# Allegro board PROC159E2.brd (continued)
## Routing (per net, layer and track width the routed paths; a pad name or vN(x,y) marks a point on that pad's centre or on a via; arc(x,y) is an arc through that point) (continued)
V3V3_XDS_FB: length 4.1
  TOP w0.381: U51.5 R332.2 ; R332.2 R333.1 ; R332.2 C248.2
VBAT_LIN: length 2.4
  TOP w0.381: D7.2 J9.1
VBAT_XDS: length 3.8
  TOP w0.381: R334.2 C262.1 33.54,87.49 v1(33.54,88.74)
  BOTTOM w0.203: U52.68 v1(33.54,88.74)
VBUS_DET: length 1.2
  BOTTOM w0.203: U17.4 103.18,13.53 R5.1
VBUS_MAIN: length 4.5
  TOP w0.381: v1(97.15,17.89) 96.9,17.64 U4.2
  BOTTOM w0.381: v1(97.75,23.8) v1(98.77,23.8) R11.1 R10.1
  vias: v1(97.15,18.78) v1(98.04,18.78) v1(98.04,17.89)
VBUS_USBC: length 18.1
  TOP w0.254: R1.1 101.96,13.55 102.08,13.68 U2.5
  TOP w0.305: 105.79,18.28 106.03,18.03 J1.A4 107.55,18.03 107.56,18.02 107.82,18.28 J1.B9 ; J1.B4 107.85,20.78 107.56,21.07 107.53,21.03 J1.A9 106.05,21.03 ; 106.05,21.03 105.66,20.64 105.66,20.43 ; 106.05,21.03 105.53,21.55 105.53,21.58
  TOP w0.381: R1.1 C2.1 v1(100.19,14.64)
  BOTTOM w0.203: U17.12 99.66,13.93 C1.1
  BOTTOM w0.254: v1(100.19,14.64) 99.67,14.64 99.41,14.39 C1.1
  BOTTOM w0.381: R6.1 103.28,10.62 103.02,10.37 R4.1 R3.1 v1(100.2,10.37) ; R5.2 v1(104.9,13.91)
  vias: v1(102.36,21.83) v1(102.36,21.07) v1(102.36,20.31) v1(102.36,19.67) v1(103.25,20.31) v1(103.25,19.67) v1(104.01,20.31) v1(104.01,19.67) v1(104.01,18.53) v1(105.02,18.53)
VBUS_XDS110: length 7.1
  TOP w0.381: U51.8 v1(17.05,103.83)
  BOTTOM w0.305: v1(15.11,99.3) 13.16,97.35 U53.6
  BOTTOM w0.381: R339.2 v1(19.93,83.05) ; R340.1 v1(21.36,103.97)
VCC2V5_PG: length 21.7
  TOP w0.254: v1(100.13,85.16) 99.49,85.8 98.62,85.8 98.06,85.24 98.06,82.79 v1(96.21,80.94) ; v1(100.13,85.16) 100.13,86.24 100.74,86.85 101.19,86.85 104.61,90.27 R81.1 ; v1(100.13,85.16) 100.47,84.82 R80.2
  BOTTOM w0.254: U14.5 v1(100.13,85.16)
  BOTTOM w0.381: v1(96.21,80.94) 95.59,80.32 93.76,80.32 93.37,80.71 U16.3
VCC3V3_XDS: length 76.7
  TOP w0.381: R354.1 v1(27.17,100.67) ; 19.98,99.86 R332.1 C248.1 ; R334.1 v1(35.56,86.22) ; R370.1 R369.1 ; R369.1 R368.1 R367.1 R366.1 R365.1 ; R369.1 v1(30.09,100.18) ; U57.1 33.33,106.68 C273.2 v1(31.64,107.28) ; R306.2 v1(37.89,78.04) 37.86,78.08 C352.1
  BOTTOM w0.203: U52.8 25.14,103.94 24.78,104.31 24.74,104.27 U52.7 ; U52.28 33.14,103.84 32.68,104.31 32.34,103.97 U52.26 ; U52.79 29.14,86.13 29.19,86.09 C252.1 ; U52.90 v1(24.74,88.72) ; C253.1 37.44,95.85 37.3,95.71 U52.47 ; U52.101 v1(22.19,90.51) ; U52.122 22.21,98.91 v1(22.22,98.92) ; C254.1 19.19,94.75 19.75,95.31 U52.113 ; C250.1 27.99,104.45 28.34,104.1 U52.16 ; C255.1 33.14,85.6 U52.69 ; U52.52 37.4,93.71 37.51,93.82 37.22,94.11 U52.51 ; U52.39 v1(34.93,98.91)
  BOTTOM w0.381: 24.78,104.31 C251.1 v1(24.78,105.91) ; R377.1 v1(18.51,82.41) ; R346.2 R345.2 v1(40.51,89) ; U31.1 C182.2 v1(40.89,87.24) ; v1(32.33,105.91) 32.68,105.56 C258.1 32.68,104.31 ; v1(38.98,93.82) C257.1 37.51,93.82 ; C253.1 v1(38.98,95.85) ; C180.2 v1(32.93,82.41) ; C180.2 34.14,81.65 R353.1 ; C180.2 U32.8 ; C254.1 v1(17.65,94.75) ; U54.8 40.91,96.25 C266.1 v1(40,96.24) 39.67,96.57 R356.1 R357.1 ; C252.1 v1(29.19,84.57) ; R348.2 v1(37.31,83.57) ; U58.1 17.24,81.14 C274.1 v1(16.51,81.17) ; R347.2 39.67,83.25 39.8,83.12 R360.1 v1(39.11,82.51) ; C255.1 v1(33.29,84.57) ; U56.1 41.21,79.97 41.11,79.87 C271.2 v1(40.41,80.48) ; C250.1 v1(27.99,105.91) ; R359.1 v1(39.11,81.24)
  vias: v1(22.22,100.06)
VCC_1V1: length 29.4
  TOP w0.254: U15.1 107.45,88.02 C97.1 107.49,87.56
  TOP w0.381: v1(99.15,78.16) 99.81,78.16 101.7,80.05 103.51,80.05 107.49,84.03 TP30.1 107.49,87.56
  BOTTOM w0.381: FL4.1 87.76,79.55 88.05,79.84 93.09,79.84 93.81,79.12 98.19,79.12 v1(99.15,78.16)
VCC_1V2: length 28.4
  TOP w0.381: v1(70.25,43.19) 70.38,43.06 C120.1 C121.1 ; U1.D10 v1(60.98,44.83) ; U1.N5 v1(56.18,36.83) ; U1.G6 v1(56.98,42.43) ; U1.G13 v1(63.38,42.43) ; U1.E9 v1(59.38,44.03) ; U1.K6 v1(56.98,39.23) ; U1.K13 v1(63.38,39.23) ; U1.G14 v1(64.18,42.43) ; U1.H3 v1(54.58,41.63) ; U1.F9 v1(59.38,43.23) ; U1.J15 v1(64.98,40.83) ; U1.N13 v1(63.38,36.83) ; U1.J16 v1(65.78,40.83) ; U1.N14 v1(64.18,36.83) ; U1.N6 v1(56.98,36.83) ; U1.E11 v1(61.78,44.03) ; U1.G5 v1(56.18,42.43) ; U1.K5 v1(56.18,39.23) ; U1.K14 v1(64.18,39.23) ; U1.R9 v1(59.38,35.23) ; U1.F11 v1(61.78,43.23)
  BOTTOM w0.305: C112.1 64.12,39.29 v1(64.18,39.23) ; v1(63.38,36.83) 63.25,36.96 C116.1 ; C133.1 61.65,43.1 v1(61.78,43.23) ; C118.1 60.87,44.72 v1(60.98,44.83) ; C124.1 64.87,40.94 v1(64.98,40.83) ; v1(56.18,39.23) 56.22,39.27 C129.1 ; C126.1 59.25,43.1 v1(59.38,43.23) 59.49,43.12 C111.1 ; C131.1 56.87,39.12 v1(56.98,39.23) 56.99,39.23 C122.1 ; C132.1 64.05,42.56 v1(64.18,42.43) ; C110.1 59.25,43.9 v1(59.38,44.03) ; C115.1 63.25,42.56 v1(63.38,42.43) ; v1(61.78,44.03) 61.89,43.92 C127.1 ; v1(56.98,36.83) 56.85,36.96 C130.1 ; C117.1 56.05,36.96 v1(56.18,36.83) ; v1(56.18,42.43) 56.29,42.54 C128.1 ; C113.1 64.05,36.96 v1(64.18,36.83) ; v1(56.98,42.43) 57.09,42.54 C125.1 ; v1(63.38,39.23) 63.27,39.34 C114.1 C123.1
  BOTTOM w0.381: R75.2 84.2,49.69 v1(84.2,49.01) ; C102.1 v1(73.87,43.19) C103.1 C119.1 v1(70.25,43.19)
  vias: v1(81.53,49.01) v1(81.53,48.12) v1(81.53,47.23) v1(82.42,49.01) v1(82.42,48.12) v1(82.42,47.23) v1(83.31,49.01) v1(83.31,48.12) v1(83.31,47.23) v1(84.2,48.12) v1(84.2,47.23)
VCC_1V2_N: length 3.8
  BOTTOM w0.108: R70.2 87.65,50.33 87.65,49.92 87.4,49.67 86.12,49.67 85.77,50.02 85.41,50.02 R75.1
VCC_1V2_P: length 3.4
  BOTTOM w0.108: R75.4 85.43,50.28 85.88,50.28 86.23,49.93 87.3,49.93 87.39,50.02 87.39,50.33 R68.2
VCC_1V8_LDO4: length 11
  TOP w0.254: v1(106.48,48.63) C72.1 106.48,47.2 106.69,46.99 U7.30
  TOP w0.381: v1(39.46,22.69) 39.45,22.7 SW7.1 ; v1(105.14,57.14) 104.45,57.14 103.92,57.68 R3833.1
  BOTTOM w0.381: TP20.1 105.14,56.51 v1(105.14,57.14) ; R36.2 v1(112.57,34.4)
VCC_2V5_EN: length 1.8
  TOP w0.147: R78.1 v1(99.21,85.16)
  BOTTOM w0.254: v1(99.21,85.16) 99.63,85.58 U14.6
VCC_5V0: length 6.3
  TOP w0.305: U29.3 23.41,22.91 C174.2
  TOP w0.381: v1(66.29,4.43) 66.66,4.43 67.04,4.05 J15.117 ; C174.2 v1(24.51,22.58)
  BOTTOM w0.381: FB1.2 24.49,22.59 v1(24.51,22.58)
VCC_6V0_BBOUT: length 12.7
  TOP w0.254: 100.69,46.22 U7.42 ; C80.1 94.96,55.92 93.13,57.75 U9.6 ; 101.19,46.33 U7.41
  TOP w0.305: 101.29,47.45 101.29,47.49
  TOP w0.381: C345.1 90.51,47.15 90.23,46.87 U66.6 ; 101.19,46.33 101.46,46.6 101.46,47.38 101.35,47.49 C31.1 101.16,47.37 100.69,46.9 100.69,46.22
  vias: v1(100.83,53.83) v1(100.83,51.8) v1(101.21,49.64) v1(101.21,48.25) v1(101.6,53.83) v1(101.6,51.8)
VCC_PLDO1: length 8.5
  TOP w0.305: U7.20 107.19,36.45 107.26,36.38 107.26,35.85 107.78,35.33 C76.1
  TOP w0.381: v1(107.78,33.56) C76.1
  BOTTOM w0.381: C74.1 110.01,35.54 110.87,35.54 111.21,35.88 111.21,37.26 J3.1
VCC_PLDO2: length 6.3
  TOP w0.254: v1(107.59,48.63) C79.1 107.59,47.24 107.19,46.84 U7.29
  BOTTOM w0.381: v1(107.82,50.91) 107.82,50.34 107.59,50.12 v1(107.59,48.63)
VDD1V1A: length 16.5
  TOP w0.381: v1(93.47,68.84) C195.1 ; C197.1 v1(87.28,75.08) ; C191.1 C192.1 85.3,68.84 v1(84.32,68.84)
  BOTTOM w0.305: U35.31 v1(84.32,68.84) ; U35.6 v1(93.47,68.84) ; U35.39 87.42,72.96 86.87,73.51 C196.1
  BOTTOM w0.381: v1(84.32,68.84) 84.31,68.86 C193.1 ; v1(85.55,76.99) 85.55,77.52 85.93,77.9 FL4.2 C190.1 ; v1(93.47,68.84) C195.1 ; C190.1 86.51,75.84 v1(87.28,75.08) 86.87,74.67 C196.1 ; C190.1 v1(85.55,75.97)
VDD2V5A: length 3
  BOTTOM w0.305: U35.9 v1(93.47,67.34) ; U35.3 v1(93.47,70.34)
  BOTTOM w0.381: C211.1 v1(93.47,70.34) ; v1(93.47,67.34) C209.1
VDD_2V5: length 10.9
  TOP w0.203: J8.4 71.69,88.24
  TOP w0.254: 103.71,86.44 104.49,87.22 C96.1 104.99,88.15 105.12,88.02 U15.4
  TOP w0.381: C221.1 71.57,88.36 71.69,88.24 ; C220.1 v1(69.59,89.14)
  BOTTOM w0.381: 103.84,86.39 102.62,86.39 102.3,86.07 U14.3 ; v1(102.65,84.09) 102.65,82.53 101.95,81.83
  vias: v1(70.48,89.14) v1(95.12,75.68) v1(95.12,74.79) v1(103.41,83.13) v1(103.41,82.16) v1(103.66,84.09)
VDD_5V0_LDO3: length 147.7
  TOP w0.305: U7.15 104.69,36.31 104.7,36.31 104.7,36.25 104.8,36.15 104.8,35.71 104.69,35.61 C69.1
  TOP w0.381: v1(60.85,75.93) R388.2 60.85,74.92 61.21,74.56 61.21,74.02 60.85,73.66 R387.2 R386.2 R385.2 ; R384.2 R383.2 R382.2 R381.2 R3834.1 73.64,77.77 v1(73.34,78.07) ; TP19.1 104.68,33.35 v1(104.68,33.74) 104.69,33.76 C69.1 ; SW4.1 v1(11.3,60.05)
  L03_SIG1 w0.381: v1(20.7,22.59) 20.7,24.86 23.23,27.39 23.23,31.68 22.27,32.63 18.39,32.63 17.45,33.57 17.45,56.5 13.9,60.05 v1(11.3,60.05)
  L05_PWR1 w0.381: v1(73.34,78.07) 73.91,78.07 74.04,78.2 76.01,78.2 77.19,79.39 80.28,79.39 82.79,76.88 83.81,76.88 86.24,74.45 86.24,73.43 87.29,72.38 92.24,72.38 94.99,69.63 94.99,61.7 95.78,60.92 95.78,59.96 101.03,54.71 106.28,54.71 107.81,53.18 108.5,53.18 110.42,51.26 110.42,44.89 109.41,43.89 109.41,39.19 107.77,37.54 106.28,37.54 104.83,36.1 104.83,35.69 104.83,35.69 104.83,34.14 104.55,33.87 v1(104.68,33.74)
  BOTTOM w0.381: FB1.1 v1(20.7,22.59)
VDD_IO_3V3: length 11
  TOP w0.381: U1.D8 v1(58.58,44.83) ; U1.D12 v1(62.58,44.83) ; U1.R15 v1(64.98,35.23) ; FL1.1 69.46,34.84 v1(69.38,34.92) ; C149.1 68.96,39.56 v1(68.83,39.69) ; U1.H15 v1(64.98,41.63) ; U1.L15 v1(64.98,38.43) ; v1(68.83,41.5) 68.96,41.37 C148.1 ; U1.P4 v1(55.38,36.03) ; U1.H4 v1(55.38,41.63)
  L06_PWR2 w0.203: v1(64.98,35.23) 65.32,34.89 65.42,34.89
  L06_PWR2 w0.381: 65.43,34.83 65.25,35.01 65.25,35.06 65.08,35.23 65.03,35.23 ; v1(64.98,35.23) 65.03,35.23 ; 65.03,35.23 65.43,35.63
  BOTTOM w0.305: v1(55.38,36.03) 55.51,36.16 C150.1 ; C153.1 64.87,38.54 v1(64.98,38.43) ; v1(55.38,41.63) 55.51,41.76 C154.1 ; v1(58.58,44.83) 58.56,44.83 C152.1 ; v1(62.58,44.83) 62.58,44.81 C156.1 ; v1(64.98,41.63) 64.87,41.74 C155.1
  BOTTOM w0.381: v1(64.98,35.23) 64.75,35.46 C139.1
  vias: v1(69.59,38.47) v1(104.39,59.04) v1(104.39,58.15) v1(105.41,59.04) v1(105.41,58.15)
VDD_IO_3V3_N: length 1.9
  BOTTOM w0.108: R74.1 101.61,57.94 100.67,57.94 R71.2
VDD_IO_3V3_P: length 1.9
  BOTTOM w0.108: R74.4 101.65,57.65 100.67,57.65 100.25,57.22 R69.2
VDD_MMC1: length 7.1
  TOP w0.381: v1(23.45,51.13) 23.49,51.17 C170.1 ; U23.5 17.51,56.25 17.9,56.64 C169.1 18.79,56.77 18.36,57.2 U23.6
  BOTTOM w0.381: J4.4 v1(23.45,51.13)
  vias: v1(22.73,56.38) v1(23.62,56.38)
VDDA1V8_OSC_PLL_F: length 2
  TOP w0.305: U1.R4 v1(55.38,35.23)
  BOTTOM w0.305: v1(55.38,35.23) 55.51,35.36 C146.1
  BOTTOM w0.381: FL2.2 v1(49.55,28.08)
VDDA3V3_F: length 4.9
  TOP w0.381: U1.P9 v1(59.38,36.03) ; v1(70.84,32.82) 70.76,32.9 FL1.2 ; U1.P11 v1(61.78,36.03) ; U1.P7 v1(57.78,36.03)
  BOTTOM w0.305: C135.1 59.25,36.16 v1(59.38,36.03) ; v1(57.78,36.03) 57.65,36.16 C137.1 ; C136.1 61.91,36.16 v1(61.78,36.03)
  BOTTOM w0.381: C134.1 71.17,33.15 v1(70.84,32.82)
VDDA_IO_1V8: length 9.8
  TOP w0.381: SW8.1 v1(32.07,24.19) ; U1.R6 v1(56.98,35.23) ; U1.R11 v1(61.78,35.23) ; R467.1 v1(51.01,33.9) ; U1.R8 v1(58.58,35.23)
  BOTTOM w0.305: C144.1 61.59,35.42 v1(61.78,35.23) ; C145.1 58.45,35.36 v1(58.58,35.23) ; C143.1 56.85,35.36 v1(56.98,35.23)
  BOTTOM w0.381: v1(51.01,33.9) 51.01,32.98 C142.1 51.12,32.88 51.12,32.14 C141.1 51.12,32.11 51.12,31.04 C140.1 50.88,29.2 FL2.1
VDDA_IO_3V3: length 25.2
  TOP w0.381: v1(52.7,23.87) 52.64,23.92 C330.2 ; v1(64.76,23.87) 64.85,23.96 C329.1 ; C316.2 59.5,23.85 v1(59.56,23.8) ; C315.1 32.84,14.5 v1(32.89,14.45) U69.5 ; U63.5 v1(27.81,14.45) ; C314.1 21.93,15.12 21.97,15.08 v1(21.97,14.45) U61.5 ; U72.16 v1(57.65,13.19) ; U73.16 51.77,12.77 v1(51.99,12.98)
  BOTTOM w0.381: v1(26.43,24.26) C284.1 27.87,24.26 27.88,24.26 U67.4 ; U74.8 v1(64.76,23.87) ; R409.1 v1(53.97,21.07) R406.1 ; U70.8 v1(59.56,23.8) ; v1(65.59,17.45) FL7.2 65.59,15.61 v1(65.37,15.39) ; U63.5 v1(27.81,14.45) 27.76,14.5 C282.1 ; U61.5 v1(21.97,14.45) ; U69.5 v1(32.89,14.45) 32.84,14.5 C315.1 ; v1(38.08,15.74) C281.1 38.1,15.03 U65.5 ; U75.8 v1(52.7,23.87)
VDDC_1V2_XDS: length 16.9
  TOP w0.381: v1(19.25,97.6) 19.25,96.94 22.73,93.46 24.38,93.46 25.98,91.86 C260.1 C259.1 25.98,88.76 v1(25.94,88.72)
  BOTTOM w0.203: U52.115 19.43,96.11 19.25,96.29 C261.1 ; U52.87 v1(25.94,88.72)
  BOTTOM w0.381: C261.1 v1(19.25,97.6)
VDDIO: length 43.4
  TOP w0.203: J8.44 71.52,96.24 C225.1
  TOP w0.381: v1(88.43,63.31) 88.43,63.12 88.82,62.74 C217.1 ; v1(107.82,55.74) 107.82,55.75 R218.1 ; C226.1 v1(69.79,96.18) ; C219.1 83.73,68.21 82.89,69.05 R225.1 R226.1 R231.2 R232.2 R230.2
  L03_SIG1 w0.381: v1(107.82,55.74) 105.21,55.74 103.09,57.86 102.26,57.86 v1(100.44,59.67)
  BOTTOM w0.254: U35.18 89.42,63.6 C216.1
  BOTTOM w0.305: C214.1 83.67,67.69 84.2,68.22 84.71,68.22 84.83,68.34 U35.30
  BOTTOM w0.381: R227.1 93.85,75.17 94.24,75.56 94.24,76.34 v1(93.54,77.04) ; v1(93.54,77.04) R228.1 ; v1(93.54,77.04) 93.9,77.4 R229.1 99.89,77.4 101.72,79.24 R216.2 ; R233.2 85.85,62.42 v1(85.72,62.29) ; C216.1 88.64,63.52 v1(88.43,63.31) ; R219.1 v1(107.82,55.74) ; FL3.1 v1(100.44,59.67) ; C214.1 v1(83.67,66.93)
  vias: v1(70.35,96.76) v1(88.87,82.71)
VDDS_IO_1V8: length 8.2
  TOP w0.305: U1.E15 v1(64.98,44.03) ; U1.N15 v1(64.98,36.83) ; U1.L4 v1(55.38,38.43) ; U1.T3 v1(54.58,34.43) ; U1.D6 v1(56.98,44.83)
  TOP w0.381: U43.5 v1(42.29,30.67) ; C108.1 v1(68.62,32.82)
  L06_PWR2 w0.381: 55.55,38.16 55.38,38.33 v1(55.38,38.43) 55.38,38.48 55.62,38.72
  BOTTOM w0.305: v1(56.98,44.83) 56.87,44.72 C106.1 ; C105.1 64.87,44.14 v1(64.98,44.03) ; v1(54.58,34.43) 54.47,34.54 C109.1 ; v1(55.38,38.43) 55.51,38.56 C107.1
  BOTTOM w0.381: C104.1 68.98,32.46 v1(68.62,32.82)
ADC1_MUX_SEL: length 51.1
  L03_SIG1 w0.091: v1(54.96,66.54) 54.96,64.79 55.43,64.32 55.43,56.08 58.52,52.99 58.52,51.3 60.17,49.64 60.17,40.07 60.37,39.87 60.37,36.89 60.84,36.42 61.2,36.42 61.39,36.23 61.39,35.88 61.64,35.62 61.94,35.62 62.17,35.39 62.17,35.39 v1(62.17,28.08)
  BOTTOM w0.147: U74.1 63.76,25.57 63.37,25.96 63.37,26.88 ; U60.15 v1(54.96,66.54) ; 63.37,26.88 63.09,27.16 62.55,27.16 62.17,27.54 v1(62.17,28.08) ; 63.37,26.88 63.66,27.17 R414.1 65.93,27.17 66.16,26.94 66.16,25.99 65.76,25.59 U74.5
ADC2_MUX_SEL: length 54.1
  L03_SIG1 w0.091: v1(54.04,66.54) 54.04,63.03 54.44,62.62 54.44,56.64 58.29,52.8 58.29,50.89 59.97,49.21 59.97,39.99 60.17,39.79 60.17,31.32 59.82,30.97 59.82,29.23 58.78,28.2 58.21,28.2 v1(57.39,27.38)
  BOTTOM w0.147: 54.1,26.92 53.85,27.17 R415.1 51.87,27.17 51.3,26.61 51.3,25.98 51.7,25.59 U75.1 ; 54.1,26.92 54.1,25.99 53.7,25.59 U75.5 ; 54.1,26.92 54.1,26.93 54.55,27.38 v1(57.39,27.38) ; U60.16 54.46,66.69 54.31,66.54 v1(54.04,66.54)
ADC3_MUX_SEL: length 58.4
  L03_SIG1 w0.091: v1(59.66,69.24) 58.3,67.88 54.69,67.88 53.56,66.76 53.56,62.73 53.93,62.36 53.93,56.78 58.03,52.68 58.03,50.76 59.77,49.03 59.77,39.91 59.97,39.71 59.97,32.27 58.37,30.68 58.37,29.28 v1(57.4,28.31)
  BOTTOM w0.147: 58.57,27.14 58.57,27.14 R405.1 60.85,27.14 61.13,26.85 61.13,26.09 60.56,25.51 U70.5 ; 58.57,27.14 v1(57.4,28.31) ; 58.57,27.14 58.57,27.13 58.17,26.72 58.17,25.94 58.56,25.55 U70.1 ; U60.6 v1(59.66,69.24)
ADC4_AIN0/ADC_CAL0/ADC_R0_AIN0: length 71.2
  TOP w0.147: U61.4 C306.1 22.92,15.67 v1(22.73,15.86) ; J15.25 v1(27.04,4.56)
  L03_SIG1 w0.091: v1(22.73,15.86) 22.73,14.56 22.44,14.27 22.44,10.96 20.59,9.11 20.59,4.71 21.37,3.93 26.41,3.93 v1(27.04,4.56)
  L08_SIG2 w0.091: v1(51.7,22.97) 48.04,19.31 43.81,19.31 40.19,15.69 40.19,13.85 33.29,6.95 31.2,6.95 29.37,5.11 27.4,5.11 26.62,5.9 25.53,5.9 24.88,6.54 24.88,8.12 23.82,9.18 23.82,12.66 22.73,13.75 v1(22.73,15.86)
  BOTTOM w0.147: U75.10 v1(51.7,22.97)
ADC4_AIN1/ADC_CAL1/ADC_R0_AIN1: length 84.5
  TOP w0.147: v1(27.04,6.59) 27.84,5.79 J15.27 ; U61.6 20.93,13.72 C307.1 20.95,15.12 20.95,15.23 v1(20.32,15.86)
  L03_SIG1 w0.091: v1(20.32,15.86) 20.58,15.6 20.58,11.75 20.94,11.38 20.94,10.47 19.91,9.43 19.91,4.8 21.29,3.42 26.5,3.42 27.47,4.38 27.47,6.16 v1(27.04,6.59)
  L08_SIG2 w0.091: v1(20.32,15.86) 20.32,15.47 23.34,12.44 23.34,7.5 26.75,4.1 32.25,4.1 33.74,5.58 34.82,5.58 36.37,7.13 36.69,7.13 40.9,11.33 40.9,15.82 43.21,18.14 47.55,18.14 52.16,22.75 52.16,23.99 52.53,24.37 53.72,24.37 v1(54.22,23.87)
  BOTTOM w0.147: U75.6 53.7,24.4 v1(54.22,23.87)
ADC4_MUX_OE#: length 2
  TOP w0.147: U72.15 57,10.24 R407.1
ADC4_MUX_SEL: length 66.1
  TOP w0.147: v1(57.01,20.43) R408.1 57.01,19.17 57.65,18.54 U72.1
  L03_SIG1 w0.091: v1(59.66,68.24) 60.3,68.88 60.3,69.42 59.99,69.72 58.84,69.72 57.4,68.28 54.67,68.28 53.29,66.91 53.29,62.74 53.64,62.39 53.64,56.73 57.75,52.62 57.75,50.66 59.33,49.09 59.33,47.1 58.97,46.75 58.97,40.3 59.77,39.5 59.77,32.61 56.52,29.35 56.52,20.93 v1(57.01,20.43)
  BOTTOM w0.147: U60.7 59.45,68.74 59.66,68.53 v1(59.66,68.24) ; v1(57.01,20.43) 57.01,20.44 R406.2
ADC5_MUX_OE#: length 1.7
  TOP w0.147: R410.1 51.06,10.61 51.12,10.68 U73.15
ADC5_MUX_SEL: length 135.4
  TOP w0.147: U73.1 51.77,18.7 51.9,18.82 R411.1 51.9,20.14 v1(51.94,20.18)
  L08_SIG2 w0.091: v1(58.46,66.54) 56.87,68.12 55.14,68.12 54.24,69.03 54.24,70.24 53.76,70.72 52.54,70.72 52.12,71.14 50.38,71.14 47.57,68.32 29.21,68.32 28.01,67.13 25.96,67.13 19.44,60.6 19.44,58.04 15.05,53.65 15.05,39.02 17.21,36.86 17.21,34.97 15.12,32.87 15.12,28.09 14.32,27.29 14.32,22.83 18.55,18.59 23.97,18.59 24.22,18.84 24.22,19.53 v1(23.84,19.91)
  BOTTOM w0.147: v1(58.46,66.54) 57.96,67.04 U60.9 ; v1(51.94,20.18) 51.97,20.21 R409.2 50.97,21.07 49.92,22.13 36.73,22.13 35.4,20.8 24.27,20.8 23.84,20.36 v1(23.84,19.91)
ADC_CAL0: length 41.5
  TOP w0.147: U1.U16 v1(65.78,33.63) ; U73.2 v1(51.12,18.78)
  L03_SIG1 w0.091: v1(51.12,18.78) 50.63,19.28 48.91,19.28 48.1,18.46 48.1,14.39 48.96,13.52 50.08,13.52 51.42,14.86 55.34,14.86 57.25,16.77 57.25,18.96 59.02,20.73 59.02,24.29 60.43,25.7 61.43,25.7 63.42,27.69 63.42,30.58 65.52,32.68 65.52,33.37 v1(65.78,33.63)
ADC_CAL0/ADC_R0_AIN0: length 10.8
  TOP w0.147: U73.4 v1(49.82,16.24)
  L08_SIG2 w0.091: v1(49.82,16.24) 49.82,19.21 52.7,22.08 v1(52.7,22.97)
  BOTTOM w0.147: U75.9 52.2,23.48 v1(52.7,22.97)
ADC_CAL1: length 12.2
  TOP w0.147: U1.T15 v1(64.98,34.43)
  L03_SIG1 w0.091: v1(64.98,34.43) 64.59,34.04 64.59,32.92 63.05,31.38 63.05,27.84 61.49,26.28 v1(60.58,26.28)
  BOTTOM w0.147: U70.4 60.06,25.76 v1(60.58,26.28)
ADC_CAL1/ADC_R0_AIN1: length 11.7
  L08_SIG2 w0.091: v1(61.87,24.42) 55.85,24.42 54.74,23.31 54.01,23.31 v1(53.46,23.86)
  BOTTOM w0.147: U70.6 60.56,24.32 60.86,24.03 61.48,24.03 v1(61.87,24.42) ; U75.7 53.2,24.13 v1(53.46,23.86)
ADC_CAL2: length 45.9
  TOP w0.147: U1.U17 v1(66.58,33.63)
  L03_SIG1 w0.091: v1(49.17,13.04) 50.11,13.04 51.57,14.5 55.49,14.5 59.9,18.91 59.9,20.06 59.39,20.57 59.39,22.13 61.04,23.77 61.04,24.27 64.16,27.39 64.16,30.18 66.58,32.6 v1(66.58,33.63)
  BOTTOM w0.147: v1(49.17,13.04) 48.49,13.72 46.7,13.72 45.76,14.66 43.95,14.66 J14.1 41.62,13.4 40.85,12.63 37.58,12.63 37.15,13.07 U65.4
ADC_CAL3: length 64.6
  TOP w0.147: U1.N17 v1(66.58,36.83)
  L03_SIG1 w0.091: v1(66.58,36.83) 69.38,36.83 71.28,34.93 71.28,32.29 69.12,30.13 69.12,28.5 69.52,28.11 69.52,26.44 67.74,24.67 67.74,23.36 64.64,20.25 64.64,19.38 62.16,16.91 61.64,16.91 60.72,15.99 60.72,13.22 55.98,8.48 51.03,8.48 50.53,8.98 47.41,8.98 46.31,10.09 44.53,10.09 41.65,12.97 41.65,14.89 J14.2
  BOTTOM w0.147: U65.6 39.05,15.16 39.83,15.94 J14.2
ADC_DAC-VREF: length 13.9
  TOP w0.381: SW7.2 37.15,25.04 37,24.89 v1(35.92,24.89)
  BOTTOM w0.381: 33.14,24.65 33.14,23.87 33.39,23.62 U67.14 ; 33.14,24.65 33.03,24.76 31.84,24.76 31.83,24.75 30.35,24.75 ; 33.14,24.65 33.38,24.89 U67.12 v1(35.92,24.89) ; 30.35,24.75 30.21,24.89 U67.5 ; 30.35,24.75 30.35,23.77 30.2,23.62 U67.3
ADC_R0_AIN0: length 37.3
  TOP w0.147: U1.T18 v1(67.38,34.43) ; v1(51.18,13.5) 50.47,14.2 U73.3
  L03_SIG1 w0.091: v1(51.18,13.5) 51.71,14.03 55.81,14.03 56.22,14.44 58.33,14.44 59.09,15.21 59.09,16.3 61.24,18.44 61.24,19.67 61.69,20.12 61.69,22.65 62.19,23.15 63.46,23.15 66.83,26.52 66.83,31.02 68.13,32.32 68.13,33.69 v1(67.38,34.43)
ADC_R0_AIN1: length 14.6
  TOP w0.147: U1.T16 v1(65.78,34.43)
  L03_SIG1 w0.091: v1(60.33,23.79) 60.59,24.05 60.59,24.34 63.78,27.54 63.78,30.36 66.17,32.75 66.17,34.04 v1(65.78,34.43)
  BOTTOM w0.147: v1(60.33,23.79) 60.33,23.83 60.06,24.09 U70.7
ADC_R0_AIN2: length 27.1
  TOP w0.147: U1.U18 v1(67.38,33.63) ; U72.3 56.35,16.21 56.99,15.57 57.28,15.57 v1(57.86,14.98)
  L03_SIG1 w0.091: v1(67.38,33.63) 67.77,33.24 67.77,32.62 65.64,30.49 65.64,29.35 65.22,28.93 65.22,26.03 64.7,25.51 64.7,25.46 64.33,25.46 62.4,23.53 61.84,23.53 60.68,22.37 60.68,18.41 57.86,15.59 v1(57.86,14.98)
ADC_R0_AIN3: length 28.8
  TOP w0.147: U72.6 54.4,15.86 55.28,14.98 v1(56.63,14.98) ; U1.T17 v1(66.58,34.43)
  L03_SIG1 w0.091: v1(56.63,14.98) 60.31,18.66 60.31,22.52 61.69,23.9 62.24,23.9 64.33,25.99 64.33,26.9 64.57,27.14 64.57,28.87 65.26,29.55 65.26,30.66 66.97,32.37 66.97,34.04 v1(66.58,34.43)
ADC_R1_AIN0: length 37.8
  TOP w0.147: U73.6 v1(48.52,14.85) ; U1.R16 v1(65.78,35.23)
  L03_SIG1 w0.091: v1(65.78,35.23) 65.39,34.84 64.04,34.84 63.79,34.59 63.79,32.77 62.6,31.57 62.6,27.9 61.63,26.93 60.48,26.93 60.07,26.52 60.07,25.97 59.13,25.04 58.03,25.04 57.25,24.25 57.25,21.72 57.8,21.16 57.8,20.04 56.88,19.11 56.88,16.92 55.25,15.3 51.33,15.3 49.94,13.91 49.09,13.91 48.52,14.47 v1(48.52,14.85)
ADC_R1_AIN1: length 24.5
  TOP w0.147: U1.R18 v1(67.38,35.23)
  L03_SIG1 w0.091: v1(67.38,35.23) 68.45,35.23 69.51,34.17 69.51,32.29 67.6,30.38 67.6,26.18 66.61,25.2 66.61,23.78 65.16,22.33 v1(62.48,22.33)
  BOTTOM w0.147: v1(62.48,22.33) 62.16,22.65 59.68,22.65 59.06,23.27 U70.9
ADC_R1_AIN2: length 36.4
  TOP w0.147: v1(53.63,12.94) 53.63,12.87 53.75,12.75 U72.10 ; U1.P18 v1(67.38,36.03)
  L03_SIG1 w0.091: v1(53.63,12.94) 54.27,13.58 56.11,13.58 56.54,14.01 58.49,14.01 59.5,15.03 59.5,15.97 61.25,17.72 61.85,17.72 63.9,19.77 63.9,20.56 67.01,23.66 67.01,25.02 67.97,25.98 67.97,30.12 69.88,32.03 69.88,34.26 70.08,34.46 70.08,34.94 69.4,35.62 67.79,35.62 v1(67.38,36.03)
ADC_R1_AIN3: length 38
  TOP w0.147: v1(55.64,10.43) 55.7,10.49 U72.13 ; U1.P17 v1(66.58,36.03)
  L03_SIG1 w0.091: v1(55.64,10.43) 59.88,14.67 59.88,15.82 61.4,17.34 62.01,17.34 64.27,19.6 64.27,20.41 67.37,23.51 67.37,24.83 69.08,26.54 69.08,27.93 68.72,28.28 68.72,30.32 70.25,31.84 70.25,33.63 70.53,33.91 70.53,35.07 69.57,36.03 68.17,36.03 67.78,36.42 66.97,36.42 v1(66.58,36.03)
ADC_VREF1: length 6.3
  TOP w0.381: SW9.3 31.06,22.71 v1(31.33,22.99)
  BOTTOM w0.381: 30.23,22.99 v1(31.33,22.99) ; 30.23,22.99 U67.2 ; 30.23,22.99 30.37,22.84 30.37,22.5 30.23,22.35 U67.1
ADC_VREF2: length 9.7
  TOP w0.381: SW9.6 27.36,22.24 27.55,22.43 v1(27.55,26.16)
  BOTTOM w0.381: U67.6 30.2,25.53 30.21,25.54 30.21,26.16 30.21,26.16 U67.7 v1(27.55,26.16)
ADC_VREF3: length 6.8
  TOP w0.381: SW13.3 35.19,22.26 v1(35.92,22.99)
  BOTTOM w0.381: v1(35.92,22.99) U67.15 33.39,22.99 33.27,22.86 33.27,22.49 33.42,22.34 34.43,22.34 U67.16
ADC_VREFHI_G0_G1: length 1.8
  TOP w0.147: SW9.2 R401.2
ADC_VREFHI_G0_G1_R: length 50.8
  TOP w0.147: U1.V10 v1(60.98,32.83) ; R401.1 33.48,18.31 36.51,15.28 38.79,15.28 40.99,17.48 v1(40.99,18.16) ; U1.V14 63.78,32.75 63.69,32.66 C287.1 C286.1 63.69,29.7 C285.1 64.63,29.61 v1(64.67,29.64)
  L08_SIG2 w0.091: v1(64.67,29.64) 63.9,28.88 63.9,27.8 61.53,25.43 52.75,25.43 47.54,20.21 43.05,20.21 v1(40.99,18.16)
  BOTTOM w0.147: v1(60.98,32.83) 60.98,31.71 63.05,29.64 v1(64.67,29.64)
ADC_VREFHI_G2: length 1.8
  TOP w0.147: SW9.5 R402.2
ADC_VREFHI_G2_R: length 55.8
  TOP w0.147: U1.V6 57.38,31.77 57.53,31.62 C289.1 57.53,30.19 C288.1 57.35,29.36 v1(57.41,29.29) ; R402.1 v1(24.51,20.27)
  L08_SIG2 w0.091: v1(24.51,20.27) 26.07,18.71 26.07,15.13 25.56,14.62 25.56,12.29 26.46,11.39 33.65,11.39 36.03,13.76 36.03,16.41 37.13,17.52 37.13,17.84 45.84,26.55 49.15,26.55 50.9,28.31 50.9,28.39 51.55,29.04 54.6,29.04 55.32,29.75 56.95,29.75 v1(57.41,29.29)
ADC_VREFHI_G3: length 2
  TOP w0.147: SW13.2 R1648.1
ADC_VREFHI_G3_R: length 38.9
  TOP w0.147: U1.V17 66.09,33.14 C350.1 66.09,30.25 C349.1 v1(66.33,29.11) ; v1(40.13,17.26) 39.45,16.58 R1648.2
  L08_SIG2 w0.091: v1(40.13,17.26) 41.01,17.26 43.55,19.8 47.49,19.8 52.71,25.03 64.03,25.03 65.19,26.18 65.19,27.97 v1(66.33,29.11)
AM263_ADC_VREFLO_1: length 8.3
  TOP w0.381: U1.V13 63.13,33.08 C287.2 ; C287.2 C286.2 63.13,29.94 C285.2 61.49,29.61 R404.2 ; C287.2 62.18,31.31 61.8,31.69 61.8,32.81 U1.V11
AM263_ADC_VREFLO_2: length 4.6
  TOP w0.381: R403.2 58.33,28.95 C288.2 58.09,30.25 C289.2 58.09,31.74 58.05,31.78 58.05,33.05 58.09,33.09 58.09,33.14 U1.V7
AM263_ADC_VREFLO_3: length 4.7
  TOP w0.381: R1649.2 65.4,29.96 C349.2 65.53,30.19 C350.2 65.53,33.08 U1.V16
AM263_DAC_VREF: length 7.9
  TOP w0.381: v1(35.92,26.16) 35.92,27.05 35.28,27.69 SW8.3
  BOTTOM w0.381: v1(35.92,26.16) U67.10 33.28,26.16 33.26,26.14 33.26,25.53 U67.11
AM263_DAC_VREF0: length 43.7
  TOP w0.381: U1.T13 v1(63.38,34.43) ; SW8.2 29.8,25.94 29.49,26.24 C279.1 ; U1.T6 v1(56.98,34.43) ; C279.1 C280.1 ; C279.1 32,27.22 32.05,27.17 v1(32.51,27.17)
  L08_SIG2 w0.091: v1(63.38,34.43) 62.99,34.82 62.99,35.37 62.74,35.62 58.42,35.62 58.17,35.37 58.17,35.07 57.94,34.84 57.39,34.84 v1(56.98,34.43) 56.59,34.04 53.3,34.04 52.62,33.36 49.85,33.36 48.51,32.02 41.73,32.02 41.09,31.37 36.71,31.37 v1(32.51,27.17)
BOOTMODE_TA_I2C_SCL: length 39.4
  TOP w0.147: v1(63.24,78.47) 63.24,77.89 R286.2 62.47,78.31 U47.12
  L08_SIG2 w0.091: v1(64.13,98.54) 63.08,97.49 63.08,91.18 62.3,90.4 62.3,83.87 62.94,83.24 62.94,81.77 63.24,81.47 v1(63.24,78.47) 62.32,78.47 61.11,79.68 58.6,79.68 56.2,82.08 52.19,82.08 v1(51.76,82.51)
  BOTTOM w0.147: R303.1 v1(64.13,98.54) ; R361.2 v1(51.76,82.51)
BOOTMODE_TA_I2C_SDA: length 40.8
  TOP w0.147: v1(64,79.09) R287.2 64.72,79.71 64.45,79.98 U47.13
  L08_SIG2 w0.091: v1(66.16,98.54) 65.25,97.63 65.25,90.54 63.79,89.08 63.79,82.45 64,82.25 v1(64,79.09) 64,78.58 63.35,77.93 62.14,77.93 60.65,79.42 58.48,79.42 56.06,81.84 51.53,81.84 v1(50.92,81.24)
  BOTTOM w0.147: R305.1 v1(66.16,98.54) ; R362.2 v1(50.92,81.24)
BOOTMODE_XDS_I2C_SCL: length 18.6
  L08_SIG2 w0.091: v1(34.79,95.27) 36.06,94 36.06,87.52 v1(40.46,83.12)
  BOTTOM w0.147: U56.3 R360.2 v1(40.46,83.12) ; v1(34.79,95.27) 35.16,94.91 U52.49
BOOTMODE_XDS_I2C_SDA: length 18.8
  L08_SIG2 w0.091: v1(40.46,81.85) 40.46,82.33 35.43,87.36 35.43,93.59 v1(34.79,94.22)
  BOTTOM w0.147: U52.50 35.08,94.51 v1(34.79,94.22) ; v1(40.46,81.85) R359.2 U56.2
BOOTMODEON: length 12.1
  BOTTOM w0.147: U48.1 66.15,85.34 66.48,85.01 67.13,85.01 67.59,85.47 ; 67.59,85.47 67.96,85.47 68.3,85.82 68.3,89.1 69.18,89.99 R329.1 68.06,92.28 R330.2 ; 67.59,85.47 67.16,85.9 U48.16
C_A5_CC1: length 10.7
  TOP w0.147: J1.A5 107.31,18.53 107.58,18.8 v1(107.58,18.91)
  BOTTOM w0.147: U17.1 101.6,14.96 102.55,15.91 102.55,16.81 103.66,17.91 105.19,17.91 106.19,18.91 v1(107.58,18.91) 107.58,18.39 D1.1
C_B5_CC2: length 13.3
  TOP w0.147: v1(107.58,20.05) 107.58,20.07 107.79,20.28 J1.B5
  BOTTOM w0.147: U17.2 102,14.77 104.45,17.23 105.31,17.23 105.57,16.97 108.07,16.97 108.45,17.35 108.45,19.18 v1(107.58,20.05) 107.58,20.71 D2.1
CLK_BUF_EN: length 79.9
  TOP w0.147: R276.1 17.77,35.49 18.12,35.84 U41.2 20.66,35.84 20.75,35.93 v1(21.2,35.93)
  L08_SIG2 w0.091: v1(59.94,72.16) 60.4,71.7 60.4,68.3 59.7,67.61 59.7,66.08 58.19,64.57 51.92,64.57 50.43,66.07 41.7,66.07 41.11,65.47 39.7,65.47 38.96,64.73 27.1,64.73 22.86,60.5 22.86,58.41 23.17,58.11 23.17,55.45 23.43,55.19 23.43,54.11 19.66,50.34 19.66,42.06 21.2,40.52 v1(21.2,35.93)
  BOTTOM w0.147: U60.2 59.33,71.24 59.52,71.43 59.52,71.73 v1(59.94,72.16)
CLK_OUT2: length 7.1
  BOTTOM w0.147: U35.40 87.92,72.81 87.91,72.82 87.91,73.21 88.96,74.26 88.96,76.04 89.15,76.22 89.15,77.85 TP62.1
CLOCKOUT0: length 55.9
  TOP w0.147: R271.1 v1(16.23,38.98) ; U1.M2 v1(53.78,37.63)
  L08_SIG2 w0.091: v1(16.23,38.98) 17.89,37.32 17.89,28.09 19.76,26.22 22.64,26.22 26.15,29.73 33.21,29.73 37.36,33.88 48.31,33.88 49.56,35.14 49.56,35.79 51.4,37.63 v1(53.78,37.63)
DIR1: length 4.2
  BOTTOM w0.147: U48.4 64.95,85.26 64.77,85.08 64,85.08 ; U48.5 64.15,85.9 63.85,85.6 63.85,85.23 64,85.08 ; 64,85.08 63.37,84.44 R322.1
EEPROM_A1: length 1.7
  BOTTOM w0.147: U28.2 R168.2
EEPROM_A2: length 1.7
  BOTTOM w0.147: U28.3 R169.2
EEPROM_WP: length 2.8
  BOTTOM w0.147: R170.2 R167.2 U28.7
EPWM11_A: length 6.4
  TOP w0.147: R3865.1 R190.1 50.2,45.09 52.32,42.98 52.32,42.29 U1.H1
ETH_LED1: length 3.2
  TOP w0.147: LD11.1 v1(68.07,75.3)
  BOTTOM w0.147: v1(68.07,75.3) 68.52,75.3 68.78,75.04 U59.3
ETH_LED2: length 3.3
  TOP w0.147: LD12.1 v1(68.07,73.27)
  BOTTOM w0.147: U59.4 68.58,73.77 v1(68.07,73.27)
ETH_LED3: length 3.9
  TOP w0.147: LD13.1 v1(68.07,71.23)
  BOTTOM w0.147: U59.5 68.83,72.5 68.07,71.74 v1(68.07,71.23)
ETH_LED4: length 4.6
  TOP w0.147: LD14.1 v1(68.07,69.2)
  BOTTOM w0.147: v1(68.07,69.2) 68.07,70.47 68.83,71.23 U59.6
ETH_LED5: length 4.7
  TOP w0.147: LD15.1 v1(66.54,69.2)
  BOTTOM w0.147: U59.11 65.53,71.23 66.54,70.22 v1(66.54,69.2)
ETH_LED6: length 4.2
  TOP w0.147: LD16.1 v1(66.54,71.23)
  BOTTOM w0.147: U59.12 65.91,72.5 66.54,71.87 v1(66.54,71.23)
ETH_LED7: length 3.5
  TOP w0.147: LD17.1 v1(66.54,73.27)
  BOTTOM w0.147: v1(66.54,73.27) 66.04,73.77 U59.13
ETH_LED8: length 3.4
  TOP w0.147: LD18.1 v1(66.54,75.3)
  BOTTOM w0.147: v1(66.54,75.3) 66.09,75.3 65.83,75.04 U59.14
EXT_VMON1: length 69.2
  TOP w0.147: v1(105.69,35.28) 105.37,35.6 105.37,35.6 105.19,35.78 U7.16 ; v1(87.8,49.37) 87.35,49.37 87.15,49.57 R55.2 R53.2 85.93,50.02 85.67,49.76 TP85.1
  L03_SIG1 w0.091: v1(110.46,58.38) 112.24,56.59 112.24,53.94 113.56,52.62 113.56,45.77 112.84,45.05 111.98,45.05 111.14,44.2 111.14,39.16 108.84,36.85 106.72,36.85 106.22,36.36 106.22,35.81 v1(105.69,35.28)
  L08_SIG2 w0.091: v1(110.46,58.38) 109.7,57.63 99.6,57.63 96.79,60.43 v1(96.79,61.09)
  BOTTOM w0.147: v1(87.8,49.37) 90.02,49.37 92.24,51.59 92.24,56.19 95.2,59.15 95.2,59.96 96.34,61.09 v1(96.79,61.09)
EXT_VMON2: length 138.5
  TOP w0.147: J8.2 72.99,87.84 v1(73.27,88.13) ; v1(102.19,36.04) U7.10
  L08_SIG2 w0.091: v1(102.19,36.04) 101.38,36.85 95.43,36.85 94.74,37.54 94.08,37.54 93.52,38.1 93.52,43.06 94.83,44.37 94.83,58.31 93.7,59.44 93.7,61.48 94.32,62.1 94.32,72.31 90.19,76.44 90.19,77.57 90.94,78.31 92.28,78.31 92.73,77.87 96.13,77.87 101.86,83.6 103.95,83.6 105.13,84.78 105.13,91.15 103.37,92.9 103.37,103.94 99.8,107.52 89.54,107.52 88.9,106.88 86.47,106.88 85.31,105.72 85.31,105.14 84.83,104.66 82.5,104.66 81.65,103.81 79.81,103.81 78.4,102.39 78.4,100.21 77.56,99.38 76.32,99.38 75.09,98.15 75.09,93.73 73.77,92.4 73.77,88.62 v1(73.27,88.13)
FSI_MUX_OE#: length 2.2
  BOTTOM w0.147: R206.1 36.34,29.79 35.76,29.22 U33.15
FSI_MUX_SEL: length 89.1
  L08_SIG2 w0.091: v1(26.79,33.9) 27.71,33.9 28.46,34.65 28.46,35.63 24.93,39.16 24.93,57.29 23.29,58.92 23.29,60.56 24.83,62.1 26.9,62.1 27.93,63.12 28.96,63.12 30.28,64.44 39.15,64.44 39.88,65.17 41.31,65.17 41.9,65.76 50.32,65.76 51.77,64.3 58.3,64.3 60.13,66.13 v1(60.13,67.43)
  BOTTOM w0.147: R205.1 R204.2 27.76,28.58 27.77,28.57 U33.1 29.92,28.57 30.04,28.69 30.36,28.69 30.68,29.01 30.68,33.11 29.89,33.9 v1(26.79,33.9) ; v1(60.13,67.43) 60.13,69.48 59.87,69.74 U60.5
FSIRX2_CLK: length 20.1
  BOTTOM w0.147: J6.1 12.79,29.92 14.45,29.92 15.14,30.61 15.14,31.56 16.39,32.81 26.1,32.81 27.09,31.82 U33.6
FSIRX2_CLK/MCAN4_TXD: length 34.9
  TOP w0.147: U1.J2 v1(53.78,40.83)
  L08_SIG2 w0.091: v1(53.78,40.83) 52.63,39.68 52.63,39.14 49.23,35.74 49.23,35.07 48.24,34.07 37.29,34.07 33.13,29.91 29.45,29.91 27.43,31.94 v1(27.43,32.47)
  BOTTOM w0.147: U33.7 v1(27.43,32.47)
FSIRX2_DATA0: length 19.6
  TOP w0.147: J6.5 17.78,29.83 23.49,29.83 25.14,31.48 32.05,31.48 v1(33.04,32.47)
  BOTTOM w0.147: U33.10 v1(33.04,32.47)
FSIRX2_DATA0/MCAN5_RXD: length 30
  TOP w0.147: U1.G4 v1(55.38,42.43)
  L08_SIG2 w0.091: v1(55.38,42.43) 54.99,42.82 52.82,42.82 51.17,41.17 51.17,39.22 48.76,36.82 48.01,36.82 46.25,35.07 42.47,35.07 42.07,35.47 39.91,35.47 39.15,34.71 34.49,34.71 v1(33.01,33.23)
  BOTTOM w0.147: U33.9 33.11,33.12 33.02,33.21 33.02,33.23 v1(33.01,33.23)
FSIRX2_DATA1: length 17.7
  BOTTOM w0.147: J6.7 20.22,27.38 29.98,27.38 31.49,28.9 31.49,29.83 32.18,30.52 U33.13
FSIRX2_DATA1/MCAN5_TXD: length 37.6
  L08_SIG2 w0.091: v1(33.02,31.17) 32.4,31.79 32.4,33.49 34.68,35.77 39.3,35.77 39.77,36.25 46.02,36.25 46.77,36.99 46.77,37.88 45.26,39.38 43.43,39.38 43.07,39.74 43.07,40.25 43.6,40.77 45.3,40.77 46,41.48 48.52,41.48 48.94,41.89 48.94,42.38 48.71,42.6 48.4,42.6 47.72,43.29 47.72,44.7 v1(48.51,45.5)
  BOTTOM w0.147: U33.12 v1(33.02,31.17) ; R193.2 v1(48.51,45.5)
FSITX2_CLK: length 58.6
  TOP w0.147: U1.G3 v1(54.58,42.43)
  L03_SIG1 w0.091: v1(20.7,26.66) 13.93,26.66 12.69,27.91 12.69,29.84 J6.2
  L08_SIG2 w0.091: v1(54.58,42.43) 54.19,42.04 53.64,42.04 52.07,40.46 52.07,38.95 48.58,35.47 48.33,35.47 48.08,35.22 48.08,34.9 47.43,34.25 37.21,34.25 33.06,30.1 30.04,30.1 28.09,32.05 28.09,32.67 27.68,33.08 26.69,33.08 24.14,30.53 24.14,28.04 22.75,26.66 v1(20.7,26.66)
FSITX2_DATA0: length 53.8
  TOP w0.147: U1.H2 v1(53.78,41.63)
  L08_SIG2 w0.091: v1(53.78,41.63) 54.19,41.22 54.19,40.59 54.97,39.81 54.97,37.47 54.72,37.22 54.33,37.22 52.11,35 49.68,35 48.39,33.7 37.44,33.7 27.09,23.35 22.37,23.35 17.66,28.07 17.66,29.95 J6.6
FSITX2_DATA1: length 11.2
  BOTTOM w0.147: U33.3 27.77,29.87 25.42,32.22 20.16,32.22 J6.8
FSITX2_DATA1/MCAN4_RXD: length 31.2
  TOP w0.147: U1.G1 v1(52.98,42.43)
  L08_SIG2 w0.091: v1(52.98,42.43) 51.62,41.07 51.62,38.77 48.69,35.83 47.81,35.83 47.19,35.22 47.19,34.8 46.83,34.43 37.14,34.43 33.23,30.52 v1(30.22,30.52)
  BOTTOM w0.147: U33.4 v1(30.22,30.52)
GPIO_ICSSM1_RST: length 17
  TOP w0.147: U1.N18 68.67,35.54 70.31,35.54 71.8,34.05 75.16,34.05 78.34,37.24 R217.1 U36.1
GPIO_ICSSM2_RST: length 92.2
  TOP w0.147: v1(67.38,37.63) U1.M18
  BOTTOM w0.147: U39.1 R265.1 71.01,99.37 70.53,98.89 70.53,97.74 69.28,96.5 69.28,95.88 69.61,95.54 69.61,95.09 70.22,94.49 70.22,92.85 69.82,92.44 69.82,90.2 68.63,89.02 68.63,85.7 68.15,85.22 68.15,84.67 67.45,83.97 67.45,81.84 66.9,81.29 64.57,81.29 62.15,78.87 62.15,72.13 60.61,70.58 60.61,67.53 61.48,66.66 64.85,66.66 65.06,66.45 65.06,64.3 63.02,62.26 63.02,57.03 67.89,52.16 70.97,52.16 71.73,51.4 71.73,49.9 71.49,49.66 71.49,47.79 71.96,47.32 74.27,47.32 74.73,46.86 75.95,46.86 76.16,46.65 76.16,46 75.93,45.77 70.03,45.77 69.19,44.94 69.19,43.02 67.87,41.7 67.87,38.12 v1(67.38,37.63)
GPIO_OSPI_RSTN: length 81.6
  L08_SIG2 w0.091: v1(60.13,73.32) 61.16,72.28 61.16,67.33 62.37,66.12 62.37,64.7 61.94,64.27 58.79,64.27 57.67,63.15 52.14,63.15 50.64,64.64 49.55,64.64 48.98,65.22 41.92,65.22 40.87,64.16 32.02,64.16 30.3,62.44 29.46,62.44 28.59,61.57 26.28,61.57 25.6,60.9 25.6,47.78 26.95,46.43 26.95,37.73 v1(29.36,35.32)
  BOTTOM w0.147: U21.1 R120.1 v1(29.36,35.32) ; v1(60.13,73.32) 59.67,73.32 58.76,72.4 U60.1
GPIO_USD_PWR_EN: length 54
  TOP w0.147: U22.2 17.86,52.31 R125.1 v1(18.12,53.42)
  L08_SIG2 w0.091: v1(18.12,53.42) 18.12,54.02 21.74,57.64 21.74,60.28 26.79,65.34 38.58,65.34 39.4,66.15 40.75,66.15 41.31,66.71 50.96,66.71 52.59,65.09 57.96,65.09 59.02,66.14 v1(59.02,67.56)
  BOTTOM w0.147: U60.8 58.76,67.82 v1(59.02,67.56)
HSEC_5V0: length 37.7
  TOP w0.381: TP81.1 103.65,8.67 v1(103.65,9.02)
  BOTTOM w0.381: v1(66.29,5.45) 67.04,4.7 J15.118 ; J15.112 64.64,3.82 64.12,4.34 64.12,5.05 v1(64.64,5.58) ; J15.180 112.04,3.78 111.23,4.59 111.23,7.7 C333.1 v1(111.39,8.57) 111.21,8.76 C332.1 ; J15.84 53.44,4.19 53.2,4.43 53.2,5.33 v1(53.44,5.58) ; J15.48 v1(35.84,5.58) ; v1(59.72,5.43) 59.04,4.74 J15.98 ; J15.158 103.24,6.88 103.65,7.29 C334.1 v1(103.65,9.02) ; R13.1 R12.1 95.05,23.54 96.26,24.75 v1(97.66,24.75)
  vias: v1(90.8,18.91) v1(92.09,18.91)
HSEC_ADC0_AIN0: length 8.8
  TOP w0.147: U1.V15 v1(64.98,32.83)
  L08_SIG2 w0.091: v1(64.98,32.83) 65.24,32.57 65.24,29.2 64.53,28.49 64.53,27.01 v1(63.88,26.36)
  BOTTOM w0.147: v1(63.88,26.36) 64.26,25.97 U74.2
HSEC_ADC0_AIN0/DAC_OUT: length 73.3
  TOP w0.147: v1(21.02,12.18) U61.1 21.02,9.94 C290.1 21.06,8.16 20.64,7.74 J15.9
  L08_SIG2 w0.091: v1(63.5,23.82) 63.23,23.55 63.23,22.42 55.31,14.5 50.74,14.5 50.23,13.99 48.23,13.99 47.35,14.87 46.59,14.87 46.23,14.51 44.57,14.51 44.17,14.12 44.17,12.61 38.73,7.16 38.73,4.45 37.54,3.25 23.3,3.25 21.02,5.54 v1(21.02,12.18)
  BOTTOM w0.147: v1(63.5,23.82) 63.5,24.12 63.76,24.38 U74.10
HSEC_ADC0_AIN1: length 10.1
  TOP w0.147: U1.U15 v1(64.98,33.63)
  L08_SIG2 w0.091: v1(65.65,26.36) 66.75,27.46 66.75,29.55 65.67,30.64 65.67,32.94 v1(64.98,33.63)
  BOTTOM w0.147: v1(65.65,26.36) 65.26,25.96 U74.4
HSEC_ADC0_AIN1/DAC_OUT: length 73.4
  TOP w0.147: J15.11 21.44,4.07 21.66,4.3 21.66,7.58 22.87,8.8 C291.1 22.92,9.94 U61.3 v1(22.92,12.18)
  L08_SIG2 w0.091: v1(65.91,23.82) 65.43,24.3 62.74,24.3 60.46,22.02 59.84,22.02 58.57,20.74 58.57,18.28 55.6,15.31 46.51,15.31 46.08,14.87 44.41,14.87 43.79,14.24 43.79,12.74 37.74,6.7 37.74,6.18 37.87,6.06 37.87,5.18 36.32,3.64 25.53,3.64 24.73,4.43 24.73,5.43 22.92,7.25 v1(22.92,12.18)
  BOTTOM w0.147: U74.6 65.76,24.09 65.91,23.94 v1(65.91,23.82)
HSEC_ADC0_AIN2: length 82.7
  TOP w0.147: J15.15 23.04,4.07 23.06,4.09 23.06,5.77 v1(22.24,6.59) ; U1.T14 v1(64.18,34.43)
  L03_SIG1 w0.091: v1(23.49,15.86) 23.49,15.49 23.4,15.4 23.4,9.92 22.24,8.76 v1(22.24,6.59)
  L08_SIG2 w0.091: v1(23.49,15.86) 23.49,15.49 23.47,15.47 23.47,13.57 24.26,12.78 24.26,9.67 26.91,7.02 27.38,7.02 28.24,6.16 28.94,6.16 30.9,8.12 33.82,8.12 39.49,13.79 39.49,17.26 42.9,20.67 47.48,20.67 52.6,25.79 61.18,25.79 63,27.62 63,29.06 64.57,30.63 64.57,34.04 v1(64.18,34.43)
  BOTTOM w0.147: v1(23.49,15.86) 22.87,15.25 C292.1 22.87,14.4 22.92,14.35 U62.6
HSEC_ADC0_AIN3: length 86.6
  TOP w0.147: U1.U14 v1(64.18,33.63) ; J15.17 v1(23.84,4.56)
  L03_SIG1 w0.091: v1(21.08,15.86) 21.64,16.43 23.81,16.43 24.32,15.91 24.32,9.34 22.95,7.97 22.95,5.07 23.47,4.56 v1(23.84,4.56)
  L08_SIG2 w0.091: v1(21.08,15.86) 21.5,16.29 23.67,16.29 24.13,15.83 24.13,14.71 24.71,14.13 24.71,11.68 25.45,10.93 25.45,9 25.49,8.95 26.41,8.03 27.22,8.03 28.14,7.11 29.02,7.11 30.43,8.52 33.7,8.52 38.96,13.78 38.96,17.25 42.91,21.19 47.47,21.19 52.24,25.96 52.24,26.5 52.52,26.78 55.65,26.78 55.84,26.59 58.38,26.59 58.63,26.84 60.09,26.84 64.18,30.93 v1(64.18,33.63)
  BOTTOM w0.147: v1(21.08,15.86) 20.93,15.72 C293.1 20.93,14.51 21.02,14.42 U62.4
HSEC_ADC0_AIN4: length 77.6
  TOP w0.147: J15.21 v1(25.44,4.56) ; U1.U13 v1(63.38,33.63) ; U63.6 26.86,14.42 26.77,14.51 C294.1 26.77,15.14 25.92,15.99 v1(25.14,15.99)
  L03_SIG1 w0.091: v1(25.44,4.56) 24.88,5.12 23.69,5.12 23.41,5.4 23.41,7.78 25.1,9.47 25.11,9.47 25.36,9.72 25.36,9.73 25.44,9.81 25.44,15.69 v1(25.14,15.99)
  L08_SIG2 w0.091: v1(63.38,33.63) 63.38,31.64 60.99,29.25 60.59,29.25 59.23,27.88 55.01,27.88 54.68,27.54 51.67,27.54 49.72,25.6 45.92,25.6 38.04,17.72 38.04,17.14 37.52,16.62 37.52,14.21 32.78,9.47 29.82,9.47 28.94,8.58 28.54,8.58 25.18,11.94 25.18,14.3 24.59,14.9 24.59,15.44 v1(25.14,15.99)
HSEC_ADC0_AIN5: length 69.5
  TOP w0.147: U1.R14 v1(64.18,35.23) ; U63.4 C295.1 28.57,15.29 v1(28.57,15.86) ; v1(25.44,6.59) 26.24,5.79 J15.23
  L03_SIG1 w0.091: v1(25.44,6.59) 25.01,7.02 25.01,7.78 25.48,8.25 26.3,8.25 27.28,9.23 27.28,14.58 v1(28.57,15.86)
  L08_SIG2 w0.091: v1(64.18,35.23) 63.79,35.62 63.79,36.22 63.59,36.42 56.02,36.42 55.79,36.19 55.79,35.02 55.62,34.84 53.33,34.84 52.82,34.33 50.16,34.33 48.3,32.47 41.54,32.47 40.9,31.83 36.57,31.83 28.13,23.39 28.13,16.31 v1(28.57,15.86)
HSEC_ADC1_AIN0: length 62.7
  TOP w0.147: U1.T11 v1(61.78,34.43)
  L03_SIG1 w0.091: v1(22.09,9.89) 21.09,8.89 v1(21.09,4.81)
  L08_SIG2 w0.091: v1(61.78,34.43) 62.17,34.04 62.17,32.95 59.91,30.7 59.74,30.52 54.99,30.52 54.35,29.89 53.75,29.89 50.63,29.89 48.24,27.5 45.68,27.5 41.78,23.6 39.64,23.6 36.21,20.17 36.21,17.9 35.24,16.94 35.24,16.09 31.71,12.56 v1(30.6,12.56)
  BOTTOM w0.147: v1(22.09,9.89) C296.1 22.92,9.94 U62.1 22.92,11.4 23.39,11.87 25.22,11.87 26.03,12.69 30.02,12.69 30.15,12.56 v1(30.6,12.56) ; J15.12 21.44,4.47 v1(21.09,4.81)
HSEC_ADC1_AIN1: length 67.3
  TOP w0.147: U1.U11 v1(61.78,33.63)
  L08_SIG2 w0.091: v1(26.03,14.34) 26.37,14 26.37,12 26.62,11.75 27.98,11.75 28.23,12 28.23,13.46 31.06,16.29 33.92,16.29 35.75,18.12 35.75,20.23 39.73,24.2 41.83,24.2 45.63,28 48.22,28 50.47,30.25 53.9,30.25 54.2,30.25 54.83,30.89 59.58,30.89 61.78,33.08 v1(61.78,33.63)
  BOTTOM w0.147: v1(26.03,14.34) 24.38,12.69 20.69,12.69 20.37,12.36 20.37,12.05 21.02,11.4 U62.3 21.02,9.94 C297.1 21.06,6.61 22.02,5.65 22.02,4.72 22.03,4.71 22.03,4.28 22.24,4.07 J15.14
HSEC_ADC1_AIN2: length 65.2
  TOP w0.147: U1.T12 v1(62.58,34.43) ; U63.1 26.9,11.19 C298.1 26.9,9.45 v1(26.67,9.22)
  L03_SIG1 w0.091: v1(26.67,9.22) 26.61,9.22 26.1,8.7 25.29,8.7 24.55,7.97 24.55,6.29 v1(23.84,5.58)
  L08_SIG2 w0.091: v1(62.58,34.43) 62.99,34.02 63.54,34.02 63.77,33.79 63.77,31.51 61.03,28.78 60.76,28.78 60.76,28.74 59.23,27.21 58.47,27.21 58.21,26.95 56.45,26.95 56.26,27.15 52,27.15 51.18,26.33 51.18,25.43 47.32,21.56 42.76,21.56 38.5,17.31 38.5,13.84 33.64,8.97 29.98,8.97 29.22,8.21 27.67,8.21 v1(26.67,9.22)
  BOTTOM w0.147: v1(23.84,5.58) 23.38,5.12 23.38,4.37 23.84,3.92 J15.18
HSEC_ADC1_AIN3: length 58.6
  TOP w0.147: U1.V12 v1(62.58,32.83) ; v1(28.76,12.18) U63.3 28.76,9.94 C299.1 28.72,9.86 27.34,8.48 24.71,8.48 v1(23.84,7.61)
  L08_SIG2 w0.091: v1(28.76,12.18) 29.13,12.18 29.18,12.13 32.24,12.13 33.92,13.81 34.9,13.81 35.66,14.58 35.66,16.7 36.67,17.72 36.67,17.9 45.81,27.04 49.12,27.04 50.44,28.37 50.44,28.45 51.49,29.49 54.5,29.49 55.12,30.12 60.82,30.12 62.58,31.88 v1(62.58,32.83)
  BOTTOM w0.147: v1(23.84,7.61) 23.84,6.51 24.64,5.71 J15.20
HSEC_ADC1_AIN4: length 60.1
  TOP w0.147: U1.U12 v1(62.58,33.63)
  L03_SIG1 w0.091: v1(28.72,9) 27.83,9 26.44,7.61 v1(25.44,7.61)
  L08_SIG2 w0.091: v1(62.58,33.63) 62.97,33.24 62.97,31.75 60.83,29.61 60.36,29.61 59.54,28.8 56.88,28.8 56.71,28.63 51.66,28.63 51.36,28.33 51.36,28.25 49.21,26.1 45.9,26.1 37.59,17.78 37.59,17.33 36.48,16.22 36.48,13.7 32.61,9.83 29.54,9.83 v1(28.72,9)
  BOTTOM w0.147: J15.24 26.24,5.15 24.98,6.4 24.98,7.15 v1(25.44,7.61) ; v1(28.72,9) C302.1 28.72,11.19 U64.1
HSEC_ADC1_AIN5: length 59.3
  TOP w0.147: U1.R12 v1(62.58,35.23)
  L08_SIG2 w0.091: v1(62.58,35.23) 62.19,34.84 60.84,34.84 60.07,34.06 60.07,32.71 58.97,31.62 54.53,31.62 53.9,30.98 49.99,30.98 49.26,30.26 47.22,30.26 46.03,29.07 44.06,29.07 42.92,27.93 42.42,27.93 34.84,20.35 34.84,18.1 34.05,17.31 31.55,17.31 26.79,12.55 v1(26.79,12.18)
  BOTTOM w0.147: J15.26 27.04,3.92 27.49,4.37 27.49,4.93 26.24,6.19 26.24,7.85 27.23,8.84 27.23,9.52 26.9,9.86 C303.1 26.9,11.19 U64.3 26.86,11.35 26.79,11.42 v1(26.79,12.18)
HSEC_ADC2_AIN0: length 35.4
  TOP w0.147: U73.5 v1(49.17,18.78) ; U1.R10 v1(60.98,35.23)
  L03_SIG1 w0.091: v1(60.98,35.23) 60.59,34.84 60.59,31.1 60.27,30.78 60.27,29.17 56.88,25.78 56.88,21.56 57.44,21.01 57.44,20.19 56.52,19.26 56.52,17.07 55.17,15.73 51.25,15.73 49.83,14.31 49.35,14.31 49.12,14.54 49.12,18.36 49.17,18.41 v1(49.17,18.78)
HSEC_ADC2_AIN0/ADC_R1_AIN0: length 42.7
  TOP w0.147: C322.1 33.84,9.94 U69.3 v1(33.84,12.18) 34.16,12.5 37.57,12.5 45,19.93 47.22,19.93 47.87,19.27 U73.7 ; v1(28.64,6.59) 29.44,5.79 J15.31
  L03_SIG1 w0.091: v1(33.84,12.18) 33.84,11.81 33.87,11.78 33.87,4.26 33.47,3.86 28.68,3.86 28.21,4.33 28.21,6.16 v1(28.64,6.59)
HSEC_ADC2_AIN1: length 11.1
  TOP w0.147: U1.T10 v1(60.98,34.43)
  L03_SIG1 w0.091: v1(60.98,34.43) 61.37,34.04 61.37,29.67 59.46,27.76 59.46,27.07 v1(58.67,26.28)
  BOTTOM w0.147: U70.2 59.06,25.94 58.71,26.28 v1(58.67,26.28)
HSEC_ADC2_AIN1/ADC_R1_AIN1: length 45.7
  TOP w0.147: 31.98,9.86 C321.1 31.94,9.94 U69.1 ; 31.98,9.86 32.73,9.11 35.26,9.11 35.68,9.53 35.68,10.61 36.43,11.35 45.15,11.35 46.53,12.73 46.53,15.07 v1(47.35,15.89) ; 31.98,9.86 29.78,7.66 29.78,4.53 30.24,4.07 J15.33
  L08_SIG2 w0.091: v1(58.29,23.79) 50.18,15.67 47.57,15.67 v1(47.35,15.89)
  BOTTOM w0.147: U70.10 58.56,24.09 58.29,23.83 v1(58.29,23.79)
HSEC_ADC2_AIN2: length 61
  TOP w0.147: C304.1 v1(39.47,9.13) 38.86,8.52 31.77,8.52 31.24,7.99 31.24,4.71 31.38,4.56 31.38,4.56 31.42,4.52 31.42,4.51 31.84,4.1 J15.37 ; U1.U10 v1(60.98,33.63)
  L08_SIG2 w0.091: v1(60.98,33.63) 60.56,33.21 60.56,32.47 59.34,31.25 54.68,31.25 54.05,30.62 50.19,30.62 48.18,28.61 45.66,28.61 43.56,26.51 41.51,26.51 35.3,20.29 v1(35.3,18.28)
  BOTTOM w0.147: v1(39.47,9.13) C304.1 39.47,10.55 39.05,10.98 U65.1 39.05,11.4 38.4,12.04 37.33,12.04 36.41,12.97 36.41,16.32 35.3,17.43 v1(35.3,18.28)
HSEC_ADC2_AIN3: length 59.2
  TOP w0.147: v1(36.46,9.15) C305.1 ; U1.T9 v1(59.38,34.43) ; v1(31.87,5.45) 32.64,4.68 J15.39
  L08_SIG2 w0.091: v1(59.38,34.43) 59.77,34.04 59.77,32.93 58.82,31.98 54.38,31.98 53.75,31.35 49.84,31.35 49.2,30.71 46.88,30.71 45.96,29.8 37.86,29.8 34.41,26.35 v1(34.41,18.28) ; v1(36.46,9.15) 32.76,5.45 v1(31.87,5.45)
  BOTTOM w0.147: v1(34.41,18.28) 34.41,17.02 35.56,15.88 35.56,12.99 37.15,11.4 U65.3 36.46,10.55 C305.1 v1(36.46,9.15)
HSEC_ADC3_AIN0: length 19.1
  TOP w0.147: v1(55.29,19.55) 55.49,19.55 57,18.04 U72.2 ; U1.U7 v1(57.78,33.63)
  L03_SIG1 w0.091: v1(57.78,33.63) 57.78,32.64 54.93,29.79 54.93,19.9 v1(55.29,19.55)
HSEC_ADC3_AIN0/ADC_R0_AIN2: length 60.8
  TOP w0.147: U72.4 55.7,18.45 53.21,20.93 44.96,20.93 39.02,14.99 36.28,14.99 34.95,16.32 34.1,16.32 v1(33.65,15.86) 33.65,15.29 C324.1 U69.4
  L03_SIG1 w0.091: v1(27.04,7.61) 27.84,6.81 27.84,4.2 28.51,3.53 33.74,3.53 34.35,4.13 34.35,9.47 35.3,10.43 35.3,16.01 34.67,16.65 34,16.65 33.65,16.3 v1(33.65,15.86)
  BOTTOM w0.147: J15.28 27.84,5.44 27.67,5.61 27.67,6.98 v1(27.04,7.61)
HSEC_ADC3_AIN1: length 21
  TOP w0.147: U1.U8 v1(58.58,33.63) ; U72.5 v1(55.05,16.21)
  L03_SIG1 w0.091: v1(58.58,33.63) 59.09,33.13 59.09,32.6 56.15,29.66 56.15,29.5 56.15,29.5 56.15,18.22 55.05,17.11 v1(55.05,16.21)
HSEC_ADC3_AIN1/ADC_R0_AIN3: length 46.1
  TOP w0.147: U72.7 53.75,19.91 53.02,20.63 45.17,20.63 37.42,12.88 32.53,12.88 31.94,13.47 U69.6 31.94,14.42 31.85,14.51 C323.1 31.85,15.25 v1(31.24,15.86)
  L03_SIG1 w0.091: v1(31.24,15.86) 30.66,15.86 29.18,14.38 29.18,12.36 29.18,12.36 29.18,12 29.18,12 29.18,6.12 v1(28.64,5.58)
  BOTTOM w0.147: J15.30 28.64,3.81 28.16,4.28 28.16,5.1 v1(28.64,5.58)
HSEC_ADC3_AIN2: length 36.6
  TOP w0.147: v1(54.52,12.94) 54.4,12.81 U72.11 ; U1.T7 v1(57.78,34.43)
  L03_SIG1 w0.091: v1(54.52,12.94) 54.02,12.44 47.23,12.44 46.68,12.99 46.68,19.35 52.52,25.19 53.18,25.19 54.47,26.47 54.47,29.91 57.39,32.84 57.39,33.79 57.78,34.18 v1(57.78,34.43)
HSEC_ADC3_AIN2/ADC_R1_AIN2: length 48.1
  TOP w0.147: v1(53.1,10.44) U72.9
  L03_SIG1 w0.091: v1(32,15.86) 31.57,15.44 31.37,15.44 30.16,14.23 30.16,7.04 30.24,6.96 v1(30.24,6.59)
  BOTTOM w0.147: v1(30.24,6.59) 29.92,6.27 29.92,4.4 30.24,4.07 J15.34 ; U68.4 31.94,14.42 31.85,14.51 C320.1 32,15.25 v1(32,15.86) 32,17.97 33.05,19.02 41.23,19.02 42.82,17.44 47.42,17.44 49.16,15.69 51.48,15.69 53.3,13.87 53.3,13.42 52.67,12.79 52.67,10.87 v1(53.1,10.44)
HSEC_ADC3_AIN3: length 40.6
  TOP w0.147: U72.14 56.35,12.91 56.42,12.98 v1(56.41,12.98) ; U1.R7 v1(57.78,35.23)
  L03_SIG1 w0.091: v1(56.41,12.98) 55.51,12.07 47.08,12.07 46.32,12.83 46.32,19.59 51.29,24.56 51.29,28.65 54.99,32.36 54.99,32.99 55.22,33.22 55.52,33.22 55.79,33.49 55.79,33.79 56.02,34.02 57.12,34.02 57.37,34.27 57.37,34.82 v1(57.78,35.23)
HSEC_ADC3_AIN3/ADC_R1_AIN3: length 46.5
  TOP w0.147: U72.12 55.05,13.31 54.81,13.55 v1(52.74,13.55)
  L03_SIG1 w0.091: v1(30.78,5.88) 32.02,5.88 33.31,7.18 33.31,14.77 v1(34.41,15.86)
  BOTTOM w0.147: U68.6 33.84,14.46 33.8,14.51 C319.1 33.8,15.25 v1(34.41,15.86) 33.68,16.6 33.68,18.18 34.22,18.73 39.78,18.73 41.49,17.02 47.23,17.02 48.96,15.3 50.99,15.3 v1(52.74,13.55) ; v1(30.78,5.88) 30.78,5.43 31.16,5.05 31.16,4.18 31.04,4.06 J15.36
HSEC_ADC3_AIN4: length 62.6
  TOP w0.147: U1.V8 v1(58.58,32.83)
  L03_SIG1 w0.091: v1(29.33,16.75) 29.6,17.01 32.1,17.01 32.88,16.23 32.88,15.34 31.89,14.34 31.89,10.4 31.32,9.83 31.32,6.89 v1(31.87,6.34)
  L08_SIG2 w0.091: v1(29.33,16.75) 29.33,22.57 37.67,30.91 41.27,30.91 41.92,31.56 48.58,31.56 49.94,32.92 52.9,32.92 53.2,33.22 58.19,33.22 v1(58.58,32.83)
  BOTTOM w0.147: U64.6 28.76,14.46 28.72,14.51 C300.1 28.72,15.14 29.33,15.76 v1(29.33,16.75) ; v1(31.87,6.34) 32.64,5.57 J15.40
HSEC_ADC3_AIN5: length 69.8
  TOP w0.147: U1.U9 v1(59.38,33.63)
  L03_SIG1 w0.091: v1(26.92,15.86) 27.38,16.32 32.15,16.32 32.43,16.04 32.43,15.53 31.43,14.53 31.43,10.59 30.73,9.89 30.73,6.44 30.36,6.06 30.36,5.56 31.65,4.27 32.45,4.27 32.61,4.43 v1(33.44,4.43)
  L08_SIG2 w0.091: v1(26.92,15.86) 27.35,15.44 28.75,15.44 30.81,17.5 30.81,23.53 37.47,30.2 42.68,30.2 43.65,31.17 48.84,31.17 49.38,31.72 53.6,31.72 54.23,32.35 58.65,32.35 59.38,33.08 v1(59.38,33.63)
  BOTTOM w0.147: U64.4 26.86,14.42 26.77,14.51 C301.1 26.77,15.72 v1(26.92,15.86) ; J15.42 v1(33.44,4.43)
HSEC_ADC4_AIN0: length 11.4
  TOP w0.147: U1.U6 v1(56.98,33.63)
  L03_SIG1 w0.091: v1(56.98,33.63) 56.57,33.22 56.02,33.22 55.79,32.99 55.79,32.49 52.24,28.94 52.24,26.78 v1(51.81,26.36)
  BOTTOM w0.147: v1(51.81,26.36) 52.2,25.97 U75.2
HSEC_ADC4_AIN1: length 9.6
  TOP w0.147: U1.V5 v1(56.18,32.83)
  L03_SIG1 w0.091: v1(53.59,26.36) 53.18,26.77 53.18,29.18 56.18,32.18 v1(56.18,32.83)
  BOTTOM w0.147: U75.4 53.2,25.96 v1(53.59,26.36)
HSEC_ADC-VREFHI: length 30.4
  TOP w0.147: SW7.3 C331.1 R418.1 v1(42.67,28.68) ; v1(35.17,6.59) 35.28,6.7 R417.2
  L03_SIG1 w0.091: v1(35.17,6.59) 35.17,9.89 35.49,10.2 35.49,16.29 36.51,17.31 36.51,22.52 v1(42.67,28.68)
HSEC_DAC_OUT: length 29.9
  TOP w0.147: U1.T5 v1(56.18,34.43)
  L03_SIG1 w0.091: v1(50.54,25.39) 50.92,25.77 50.92,28.81 54.59,32.47 54.59,33.39 55.23,34.02 55.61,34.02 56.02,34.43 v1(56.18,34.43)
  BOTTOM w0.147: R413.2 R412.2 62.76,21.89 62.61,21.75 58.97,21.75 58.25,22.46 51.56,22.46 50.54,23.49 v1(50.54,25.39)
HSEC_EPWM0_A: length 56.7
  TOP w0.147: J15.49 v1(36.64,4.56) ; U1.B2 v1(53.78,46.43)
  L03_SIG1 w0.091: v1(36.64,4.56) 36.25,4.56 35.41,5.4 35.41,5.75 35.85,6.19 35.85,16.14 37.76,18.05 37.76,21.6 42.53,26.37 43.59,26.37 46.45,29.23 46.45,30.28 49.49,33.33 49.49,37.69 50.04,38.24 50.04,45.79 51.86,47.62 53.14,47.62 53.37,47.39 53.37,46.88 53.78,46.46 v1(53.78,46.43)
HSEC_EPWM0_B: length 53.3
  TOP w0.147: U1.B1 v1(52.98,46.43) ; v1(36.64,6.59) 37.09,6.59 37.89,5.79 37.89,5.12 37.44,4.66 J15.51
  L03_SIG1 w0.091: v1(52.98,46.43) 52.61,46.43 50.47,44.29 50.47,38.03 49.86,37.42 49.86,33.12 46.81,30.07 46.81,29.08 38.17,20.44 38.17,17.94 36.52,16.29 36.52,10.99 36.96,10.55 36.96,8.46 37.41,8.01 37.41,7.36 v1(36.64,6.59)
